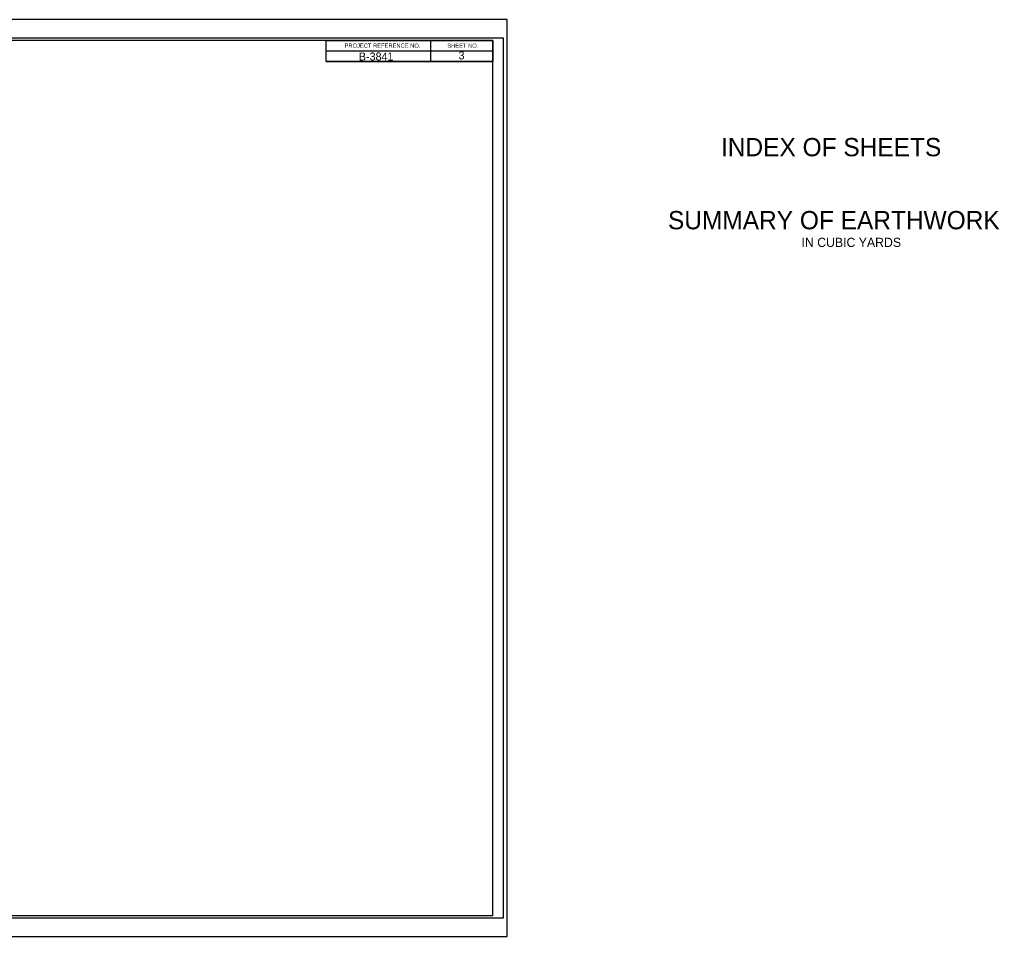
# Model space of a CAD drawing. Extents: x 573359 to 575895, y -54193 to -50493.
# Drawn here: x 574719 to 575895, y -54193 to -53093 of the extents above; entities that cross this region are included whole.
import ezdxf

# ---------------------------------------------------------------- set-up
doc = ezdxf.new("R2010")
doc.units = 0
for name, color, linetype in [('Prop Dimension Text', 7, 'Continuous'), ('Sheet Cutting Line CELL', 7, 'Continuous'), ('Sheet Plot Border Inside CELL', 7, 'Continuous'), ('Sheet Plot Border Outside CELL', 7, 'Continuous'), ('Sheet Summary CELL', 7, 'Continuous')]:
    doc.layers.add(name, color=color, linetype=linetype)

msp = doc.modelspace()

# ---------------------------------------------------------------- linework, layer by layer
at = {"layer": 'Sheet Cutting Line CELL'}
for p, q in [((575304.2, -53092.8), (573620.2, -53092.8)), ((573620.2, -54192.8), (575304.2, -54192.8))]:
    msp.add_line(p, q, dxfattribs=at)
at = {"layer": 'Sheet Plot Border Inside CELL'}
msp.add_lwpolyline([(575299.7, -53115.3), (573633.2, -53115.3), (573633.2, -54170.4), (575299.7, -54170.4)], close=True, dxfattribs=at)
at = {"layer": 'Sheet Plot Border Outside CELL'}
msp.add_lwpolyline([(575304.2, -53092.8), (573620.2, -53092.8), (573620.2, -54192.8), (575304.2, -54192.8)], close=True, dxfattribs=at)
at = {"layer": 'Sheet Summary CELL'}
for p, q in [((575212.2, -53117.9), (575212.2, -53142.9)), ((575087.1, -53130.4), (575287.2, -53130.4)), ((575087.1, -53142.9), (575287.2, -53142.9))]:
    msp.add_line(p, q, dxfattribs=at)
for points in [[(575287.2, -53117.8), (573787.2, -53117.8), (573787.2, -54167.8), (575287.2, -54167.8)], [(575087.1, -53117.8), (575287.2, -53117.8), (575287.2, -53142.9), (575087.1, -53142.9)]]:
    msp.add_lwpolyline(points, close=True, dxfattribs=at)

# ---------------------------------------------------------------- texts
at = {"layer": 'Prop Dimension Text'}
for s, p in [('B-3841', (575126.5, -53141.9)), ('3', (575246, -53140.6))]:
    msp.add_text(s, height=9.6, dxfattribs=at).set_placement(p)
at = {"layer": 'Sheet Summary CELL'}
for s, height, p in [('PROJECT REFERENCE NO.', 5, (575109.3, -53126.5)), ('SHEET NO.', 5, (575232.5, -53126.6)), ('INDEX OF SHEETS', 21.95, (575560.8, -53256.8)), ('SUMMARY OF EARTHWORK', 21.95, (575497.2, -53344.4)), ('IN CUBIC YARDS', 11, (575657.4, -53365.6))]:
    msp.add_text(s, height=height, dxfattribs=at).set_placement(p)

doc.saveas('drawing.dxf')
